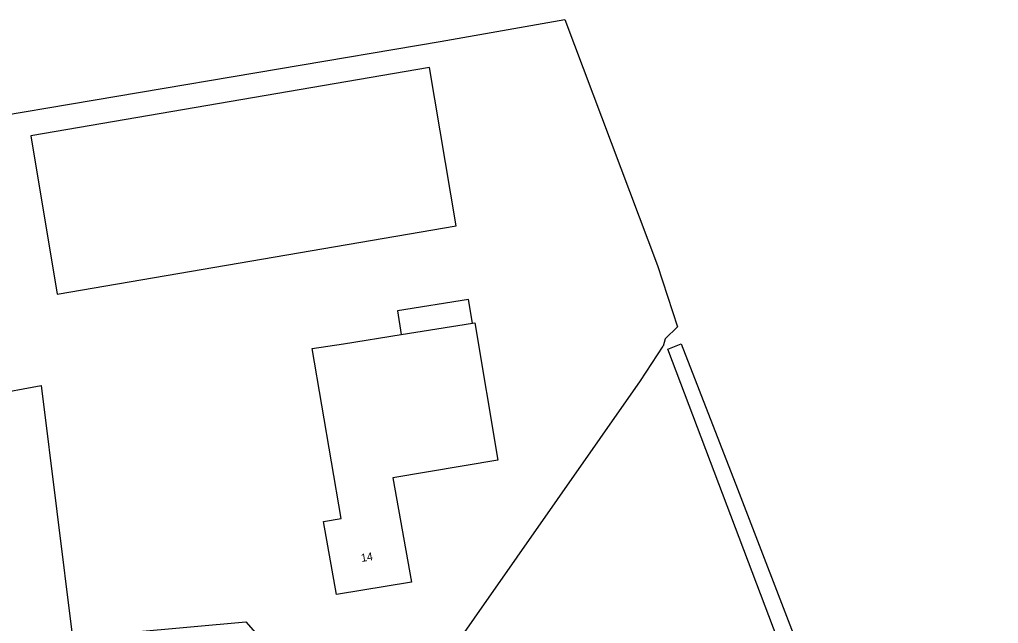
# Model space of a CAD drawing. Extents: x 135990 to 139000, y 393500 to 396000.
# Drawn here: x 137206.8 to 137329.1, y 395310.3 to 395385.7 of the extents above; entities that cross this region are included whole.
import ezdxf

# ---------------------------------------------------------------- set-up
doc = ezdxf.new("R2010")
doc.units = 0
for name, color, linetype in [('gg-afsc-lijn draadraster', 7, 'Continuous'), ('gg-anno-huisnummerreeks BGT', 7, 'Continuous'), ('gg-bbg-bijgebouw', 7, 'Continuous'), ('gg-bbg-gedigitaliseerde bebouwing', 7, 'Continuous'), ('gg-bbg-hoofdgebouw', 7, 'Continuous'), ('gg-bbg-luifel en loopbrug', 7, 'Continuous'), ('gg-kntw-bovenkant insteek waterloop', 7, 'Continuous'), ('gx-grn-maaiveld', 7, 'Continuous')]:
    doc.layers.add(name, color=color, linetype=linetype)

msp = doc.modelspace()

# ---------------------------------------------------------------- linework, layer by layer
at = {"layer": 'gg-afsc-lijn draadraster'}
msp.add_lwpolyline([(137269.371, 395233.055), (137261.716, 395278.808), (137258.933, 395299.464), (137258.582, 395303.732), (137284.331, 395340.556), (137287.177, 395344.907)], dxfattribs=at)
at = {"layer": 'gg-bbg-bijgebouw'}
msp.add_lwpolyline([(137211.467, 395351.396), (137261.334, 395359.923), (137258.009, 395379.682), (137208.2, 395371.154), (137211.467, 395351.396)], dxfattribs=at)
at = {"layer": 'gg-bbg-gedigitaliseerde bebouwing'}
for p, q in [((137254.464, 395346.334), (137263.35, 395347.765)), ((137263.35, 395347.765), (137263.646, 395347.813)), ((137263.646, 395347.813), (137266.53, 395330.652)), ((137247.24, 395345.171), (137254.464, 395346.334)), ((137243.32, 395344.612), (137247.24, 395345.171))]:
    msp.add_line(p, q, dxfattribs=at)
at = {"layer": 'gg-bbg-hoofdgebouw'}
msp.add_lwpolyline([(137266.53, 395330.652), (137253.41, 395328.462), (137255.74, 395315.432), (137246.36, 395313.872), (137244.77, 395323.01), (137246.94, 395323.381), (137243.32, 395344.612)], dxfattribs=at)
at = {"layer": 'gg-bbg-luifel en loopbrug'}
msp.add_lwpolyline([(137263.35, 395347.765), (137262.873, 395350.727), (137253.987, 395349.296), (137254.464, 395346.334)], dxfattribs=at)
at = {"layer": 'gg-kntw-bovenkant insteek waterloop'}
msp.add_lwpolyline([(137329.051, 395242.384), (137326.785, 395241.552), (137287.757, 395344.533), (137289.429, 395345.167), (137296.448, 395327.072), (137329.051, 395242.384)], dxfattribs=at)
at = {"layer": 'gx-grn-maaiveld'}
for points in [[(137133.367, 395233.429), (137140.052, 395246.83), (137148.762, 395264.993), (137161.242, 395291.759), (137175.316, 395321.712), (137186.575, 395346.142), (137193.452, 395361.729), (137198.69, 395372.696), (137259.306, 395382.946), (137274.89, 395385.662), (137286.479, 395354.944), (137288.987, 395347.292), (137287.427, 395345.823), (137287.177, 395344.907)], [(137268.725, 395232.787), (137261.716, 395278.808), (137258.933, 395299.464), (137258.582, 395303.732), (137284.331, 395340.556), (137287.177, 395344.907)], [(137143.09, 395227.239), (137146.141, 395233.068), (137152.78, 395247.062), (137159.657, 395261.773), (137168.287, 395280.069), (137173.625, 395291.673), (137178.723, 395302.719), (137183.981, 395313.66), (137187.008, 395320.404), (137190.672, 395328.291), (137192.584, 395332.141), (137195.558, 395334.876), (137199.223, 395337.186), (137203.153, 395338.806), (137209.499, 395339.975), (137213.407, 395308.516), (137235.049, 395310.476), (137236.828, 395308.422)]]:
    msp.add_lwpolyline(points, dxfattribs=at)

# ---------------------------------------------------------------- texts
at = {"layer": 'gg-anno-huisnummerreeks BGT'}
msp.add_text('14', height=1, rotation=9.4, dxfattribs=at).set_placement((137249.512, 395317.945))

doc.saveas('drawing.dxf')
